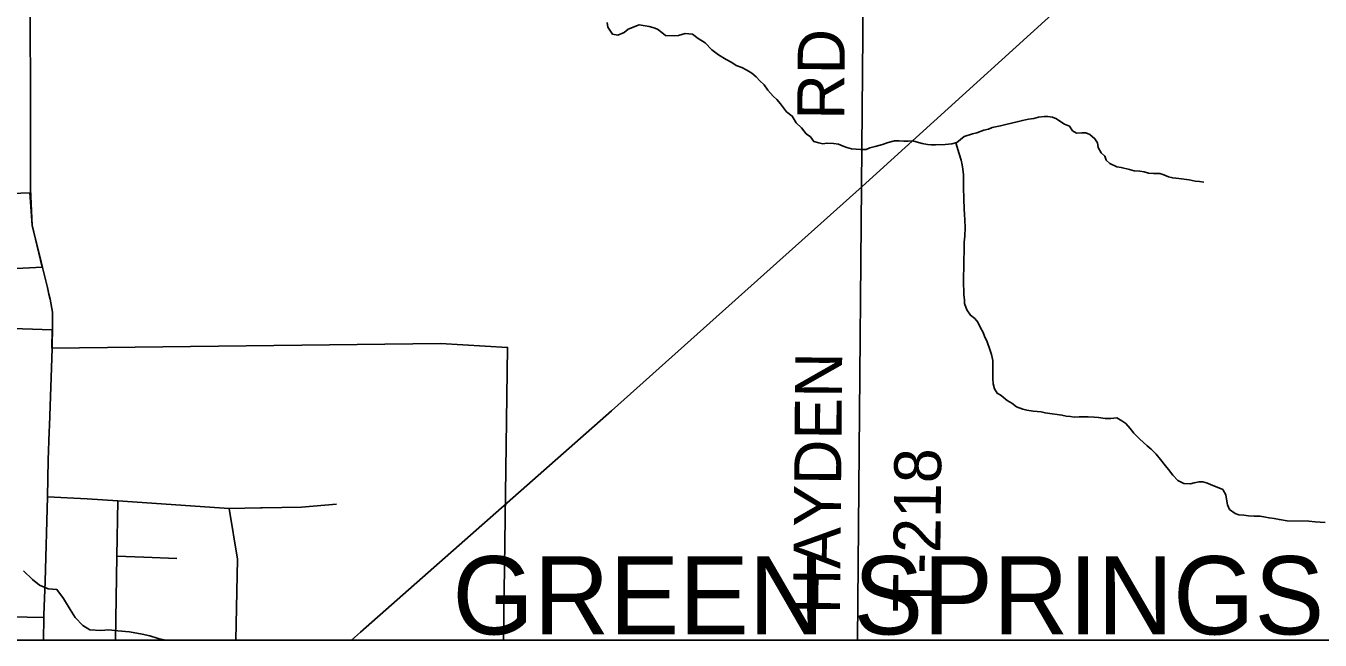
# Model space of a CAD drawing. Extents: x 0 to 34, y 0 to 22.
# Drawn here: x 26.932 to 28.499, y 14.1 to 14.843 of the extents above; entities that cross this region are included whole.
import ezdxf

# ---------------------------------------------------------------- set-up
doc = ezdxf.new("R2010")
doc.units = 0
for name, color, linetype in [('GM_X_City_Street', 7, 'Continuous'), ('GM_X_Corporation_Text', 7, 'Continuous'), ('GM_X_Minor_River', 7, 'Continuous'), ('GM_X_Rail_Line', 7, 'Continuous'), ('GM_X_State_Route', 7, 'Continuous'), ('GM_X_Township_Road', 7, 'Continuous'), ('GM_X_Township_Road_Text', 7, 'Continuous'), ('SH_Data', 7, 'Continuous')]:
    doc.layers.add(name, color=color, linetype=linetype)

msp = doc.modelspace()

# ---------------------------------------------------------------- linework, layer by layer
at = {"layer": 'GM_X_City_Street'}
for points in [[(26.8663, 14.5471), (26.9519, 14.5515), (26.9396, 14.6022), (26.9369, 14.6413), (26.8704, 14.6389)], [(26.4312, 14.1), (27.5103, 14.1), (27.5153, 14.4542), (27.4341, 14.4589), (26.9636, 14.4533), (26.9639, 14.4755), (26.8676, 14.4786)], [(26.9583, 14.2736), (27.0062, 14.2709), (27.0432, 14.2685), (27.1782, 14.2594), (27.2159, 14.2601), (27.2179, 14.2602)], [(27.0405, 14.1), (27.042, 14.2017), (27.0432, 14.2685)], [(27.1861, 14.1), (27.1881, 14.1979), (27.1782, 14.2594)], [(27.2179, 14.2602), (27.2658, 14.2611), (27.3079, 14.2644)], [(27.042, 14.2017), (27.0747, 14.2005), (27.1148, 14.1987)], [(26.8294, 14.1507), (26.8679, 14.1413), (26.8936, 14.1326), (26.9134, 14.1281), (26.9539, 14.1274)]]:
    msp.add_lwpolyline(points, dxfattribs=at)
at = {"layer": 'GM_X_Minor_River'}
for points in [[(27.6358, 14.8475), (27.6368, 14.8418), (27.6424, 14.8334), (27.6489, 14.8322), (27.6565, 14.8355), (27.6611, 14.8396), (27.6744, 14.8448), (27.6865, 14.8428), (27.6911, 14.8416), (27.6967, 14.8396), (27.702, 14.8354), (27.7065, 14.8316), (27.7175, 14.8314), (27.7221, 14.8318), (27.7304, 14.8343), (27.7392, 14.8335), (27.7459, 14.8281), (27.7546, 14.8231), (27.7625, 14.8143), (27.7707, 14.8085), (27.7798, 14.8027), (27.7866, 14.7992), (27.7918, 14.7953), (27.799, 14.793), (27.805, 14.7899), (27.8111, 14.7864), (27.8163, 14.7818), (27.8208, 14.7768), (27.8257, 14.7722), (27.8302, 14.7657), (27.8369, 14.7584), (27.8414, 14.7542), (27.8455, 14.7492), (27.853, 14.7396), (27.8598, 14.7343), (27.8646, 14.7259), (27.871, 14.7201), (27.8766, 14.7128), (27.8819, 14.709), (27.886, 14.7036), (27.892, 14.702), (27.897, 14.7008), (27.9019, 14.7015), (27.9099, 14.7011), (27.9159, 14.7002), (27.9216, 14.6979), (27.9261, 14.6963), (27.9318, 14.6948), (27.9428, 14.6939), (27.9492, 14.6938), (27.9538, 14.696), (27.9603, 14.6975), (27.969, 14.6997), (27.9759, 14.7023), (27.9835, 14.7045)], [(27.9835, 14.7045), (27.9892, 14.7044), (27.9949, 14.704), (28.0002, 14.7039), (28.0059, 14.7042), (28.0127, 14.7022), (28.0172, 14.7011), (28.0236, 14.6999), (28.0282, 14.6994), (28.0335, 14.6994), (28.0449, 14.7), (28.0529, 14.7007), (28.0593, 14.7021), (28.0681, 14.7096), (28.078, 14.7129), (28.0834, 14.714), (28.0917, 14.7173), (28.0974, 14.7184), (28.102, 14.7203), (28.1119, 14.7224), (28.1199, 14.7243), (28.1321, 14.7272), (28.1385, 14.729), (28.1458, 14.7304), (28.1522, 14.7315), (28.1579, 14.733), (28.1648, 14.7336), (28.1693, 14.7336), (28.175, 14.7328), (28.1799, 14.7308), (28.1852, 14.7274), (28.1897, 14.7246), (28.1957, 14.7219), (28.1991, 14.7166), (28.204, 14.7135), (28.2104, 14.7138), (28.2154, 14.7141), (28.2203, 14.7118), (28.2263, 14.7068), (28.2296, 14.7018), (28.2303, 14.6961), (28.2337, 14.6896), (28.2382, 14.6858), (28.24, 14.6808), (28.2445, 14.677), (28.2528, 14.6727), (28.2581, 14.6719), (28.2683, 14.6695), (28.274, 14.6679), (28.2808, 14.6675), (28.2861, 14.6667), (28.2914, 14.6651), (28.2971, 14.6647), (28.3051, 14.6646), (28.3096, 14.663), (28.3153, 14.6607), (28.3206, 14.6595), (28.3281, 14.6586), (28.3403, 14.657), (28.3478, 14.6554), (28.3531, 14.6549), (28.3581, 14.6541)], [(28.058, 14.7018), (28.0618, 14.6884), (28.0644, 14.6808), (28.0658, 14.6751), (28.0665, 14.6702), (28.0672, 14.6633), (28.0671, 14.6478), (28.0677, 14.6341), (28.0679, 14.6216), (28.0686, 14.6155), (28.0689, 14.6083), (28.0692, 14.5995), (28.0687, 14.5889), (28.0682, 14.5817), (28.0681, 14.5699), (28.0676, 14.5612), (28.0672, 14.5297), (28.0675, 14.524), (28.0678, 14.5179), (28.0685, 14.5118), (28.0685, 14.5073), (28.0714, 14.4997), (28.0755, 14.4932), (28.0808, 14.4893), (28.0845, 14.4847), (28.0875, 14.4786), (28.0909, 14.4725), (28.0927, 14.4679), (28.096, 14.4611), (28.099, 14.4519), (28.1012, 14.4458), (28.1026, 14.4386), (28.1029, 14.4318), (28.1027, 14.4166), (28.103, 14.4101), (28.1049, 14.404), (28.1078, 14.3987), (28.1127, 14.396), (28.1199, 14.3902), (28.1259, 14.3867), (28.1312, 14.3825), (28.1391, 14.3794), (28.144, 14.3782), (28.1516, 14.3769), (28.1614, 14.3761), (28.166, 14.3749), (28.1747, 14.374), (28.1808, 14.3732), (28.1864, 14.3724), (28.1917, 14.3712), (28.1967, 14.3708), (28.2012, 14.37), (28.2073, 14.3703), (28.2183, 14.3702), (28.2255, 14.3697), (28.2308, 14.3693), (28.2387, 14.3684), (28.2456, 14.3683), (28.2528, 14.369), (28.2588, 14.3652), (28.2637, 14.3621), (28.2689, 14.3563), (28.2734, 14.3506), (28.2802, 14.3437), (28.2896, 14.3352), (28.2945, 14.331), (28.3005, 14.3252), (28.3057, 14.3187), (28.3117, 14.3111), (28.3154, 14.3065), (28.3206, 14.2996), (28.3266, 14.2931), (28.3338, 14.2896), (28.3421, 14.2891), (28.3467, 14.2902), (28.3524, 14.2917), (28.357, 14.2916), (28.3626, 14.29), (28.3672, 14.2881), (28.3743, 14.2853), (28.3811, 14.2822), (28.3849, 14.2757), (28.3856, 14.2704), (28.387, 14.2636), (28.3892, 14.2582), (28.396, 14.2532), (28.4005, 14.2517), (28.4066, 14.2512), (28.4123, 14.2504), (28.4191, 14.2499), (28.4263, 14.2499), (28.4327, 14.249), (28.4373, 14.2479), (28.4433, 14.247), (28.4498, 14.2458), (28.4592, 14.2442), (28.4854, 14.2439), (28.493, 14.2431), (28.5051, 14.2422)], [(26.9291, 14.1839), (26.94, 14.1732), (26.9487, 14.1666), (26.9592, 14.162), (26.9695, 14.1611), (26.9777, 14.1504), (26.9855, 14.137), (26.9918, 14.1275), (27.0008, 14.1175), (27.0095, 14.1125), (27.0228, 14.1116), (27.0326, 14.1126), (27.0432, 14.1113), (27.0573, 14.1101), (27.0728, 14.1072), (27.0819, 14.1052), (27.0921, 14.1021), (27.1009, 14.1)]]:
    msp.add_lwpolyline(points, dxfattribs=at)
at = {"layer": 'GM_X_Rail_Line'}
msp.add_lwpolyline([(27.3262, 14.1), (27.337, 14.1097), (27.6409, 14.3774), (27.9444, 14.6491), (28.2526, 14.9288), (28.5584, 15.2053)], dxfattribs=at)
at = {"layer": 'GM_X_State_Route'}
for points in [[(26.9378, 14.6458), (26.9373, 14.9656), (26.9419, 15.2988), (26.9497, 15.6998), (26.956, 16.1074)], [(26.9505, 14.5577), (26.9398, 14.6017), (26.9378, 14.6458)], [(26.9599, 14.5188), (26.9581, 14.5269), (26.9556, 14.5365), (26.9521, 14.551), (26.9505, 14.5577)], [(26.9641, 14.4789), (26.9644, 14.4971), (26.9614, 14.5127), (26.9599, 14.5188)], [(26.9639, 14.4595), (26.9641, 14.4749), (26.9641, 14.4789)], [(26.9605, 14.3596), (26.9638, 14.4528), (26.9639, 14.4595)], [(26.9539, 14.1304), (26.9552, 14.1711), (26.9583, 14.2736), (26.9592, 14.3179), (26.9603, 14.3526), (26.9605, 14.3596)], [(26.9534, 14.1), (26.9539, 14.1274), (26.9539, 14.1304)]]:
    msp.add_lwpolyline(points, dxfattribs=at)
at = {"layer": 'GM_X_Township_Road'}
msp.add_line((27.9387, 14.1), (27.9464, 14.9347), dxfattribs=at)
at = {"layer": 'SH_Data'}
msp.add_lwpolyline([(23.5167, 20.9), (30.3167, 20.9), (30.3167, 14.1), (23.5167, 14.1)], close=True, dxfattribs=at)

# ---------------------------------------------------------------- texts
at = {"layer": 'GM_X_Corporation_Text'}
msp.add_text('GREEN SPRINGS', height=0.094697, rotation=0, dxfattribs=at).set_placement((27.4485, 14.1069))
at = {"layer": 'GM_X_Township_Road_Text'}
for s, rotation, p in [('RD', 89.5063, (27.9227, 14.7297)), ('HAYDEN', 89.512, (27.9177, 14.1313)), ('T-218', 89.4386, (28.0385, 14.1335))]:
    msp.add_text(s, height=0.05682, rotation=rotation, dxfattribs=at).set_placement(p)

doc.saveas('drawing.dxf')
